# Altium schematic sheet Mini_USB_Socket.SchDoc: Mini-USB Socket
size A4; DocumentNumber: 8; SheetNumber: 8; SheetTotal: 12
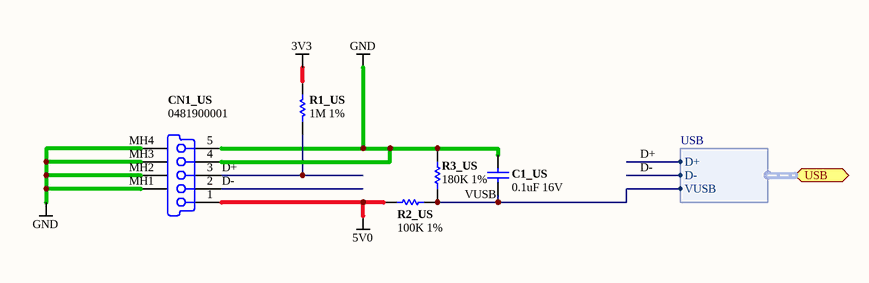
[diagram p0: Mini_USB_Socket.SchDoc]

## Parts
C1_US  0.1uF 16V  [CAPC1005-STAR]
CN1_US  0481900001  [481900001]
R1_US  1M 1%  [RESC1005-STAR]
R2_US  100K 1%  [RESC1005-STAR]
R3_US  180K 1%  [RESC1005-STAR]

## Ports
USB (harness USB)

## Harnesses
USB: VUSB, D-, D+

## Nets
3V3: R1_US.2
5V0: CN1_US.1 R2_US.2
GND: C1_US.1 CN1_US.4 CN1_US.5 CN1_US.MH1 CN1_US.MH2 CN1_US.MH3 CN1_US.MH4 R3_US.2
D+: CN1_US.3 R1_US.1 ; port USB.D+
D-: CN1_US.2 ; port USB.D-
VUSB: C1_US.2 R2_US.1 R3_US.1 ; port USB.VUSB

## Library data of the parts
C1_US = D-101-0080: Capacitor, Ceramic, 0.1uF 10% 16V 0402 (1005) X7R; Polarity: Non-Polarized
CN1_US = D-300-0034: USB On-The-Go (OTG) Mini-B Receptacle, Right Angle, SMT, 0.80mm (.031") Pitch, Solder Tabs with Back Cover, Recessed Type; Max Current: mA
R1_US = D-100-0075: Resistor, 1M 1% 0402; Power Rating: mW; Resistance: mR; Tolerance: %
R2_US = D-100-0132: Resistor, 100K 1% 0402 (1005); Power Rating: 63 mW
R3_US = D-100-0006: Resistor, 180K 1% 0402 (1005); Power Rating: 63 mW; Tolerance: %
